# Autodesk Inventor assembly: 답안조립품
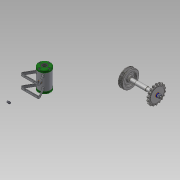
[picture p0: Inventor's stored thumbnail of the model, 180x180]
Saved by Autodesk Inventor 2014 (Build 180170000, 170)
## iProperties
Created: 2016-03
Part Number: 답안조립품
Document SubType Name: Assembly
Designer: user
Author: user
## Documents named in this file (16)
- C:\Users\user\Desktop\460308V1007\답안조립품.iam
- C:\Users\user\Desktop\460308V1007\V벨트풀리.ipt
- C:\Users\user\Desktop\460308V1007\너트 M 8.ipt
- C:\Users\user\Desktop\460308V1007\니플 M 6 x 0.75.ipt
- C:\Users\user\Desktop\460308V1007\베어링 15 x 32 x 9.ipt
- C:\Users\user\Desktop\460308V1007\본체.ipt
- C:\Users\user\Desktop\460308V1007\볼트 M 6 x 8.ipt
- C:\Users\user\Desktop\460308V1007\볼트 M4 x 12.ipt
- C:\Users\user\Desktop\460308V1007\스프로킷.ipt
- C:\Users\user\Desktop\460308V1007\스프링와셔 8.ipt
- C:\Users\user\Desktop\460308V1007\오일 실 15 25 7.ipt
- C:\Users\user\Desktop\460308V1007\와셔 6x11.5.ipt
- C:\Users\user\Desktop\460308V1007\와셔 8x17.ipt
- C:\Users\user\Desktop\460308V1007\축.ipt
- C:\Users\user\Desktop\460308V1007\커버.ipt
- C:\Users\user\Desktop\460308V1007\키 3 x 3 x 12.ipt
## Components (11 placed, 3 different names)
1. V벨트풀리:1 — Mate:28, Mate:29, Mate:30, Mate:32
2. KS B 2023 6002 - 15 x 32 x 9:1 — Mate:5, Mate:6
3. KS B 2023 6002 - 15 x 32 x 9:2 — Mate:3, Mate:4, Mate:10
4. ISO 4762 M4 x 12:1 — Mate:15, Mate:16
5. ISO 4762 M4 x 12:3
6. ISO 4762 M4 x 12:4
7. ISO 4762 M4 x 12:5
8. ISO 4762 M4 x 12:2 — Mate:17, Mate:18
9. ISO 4762 M4 x 12:6
10. ISO 4762 M4 x 12:7
11. ISO 4762 M4 x 12:8
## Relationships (13: Mate 13)
- Mate:3: KS B 2023 6002 - 15 x 32 x 9:2
- Mate:4: KS B 2023 6002 - 15 x 32 x 9:2
- Mate:5: KS B 2023 6002 - 15 x 32 x 9:1
- Mate:6: KS B 2023 6002 - 15 x 32 x 9:1
- Mate:10: KS B 2023 6002 - 15 x 32 x 9:2
- Mate:15: ISO 4762 M4 x 12:1
- Mate:16: ISO 4762 M4 x 12:1
- Mate:17: ISO 4762 M4 x 12:2
- Mate:18: ISO 4762 M4 x 12:2
- Mate:28: V벨트풀리:1
- Mate:29: V벨트풀리:1
- Mate:30: V벨트풀리:1
- Mate:32: V벨트풀리:1
## Named parameters: d6_d0 = 0, d7_d1 = 0
